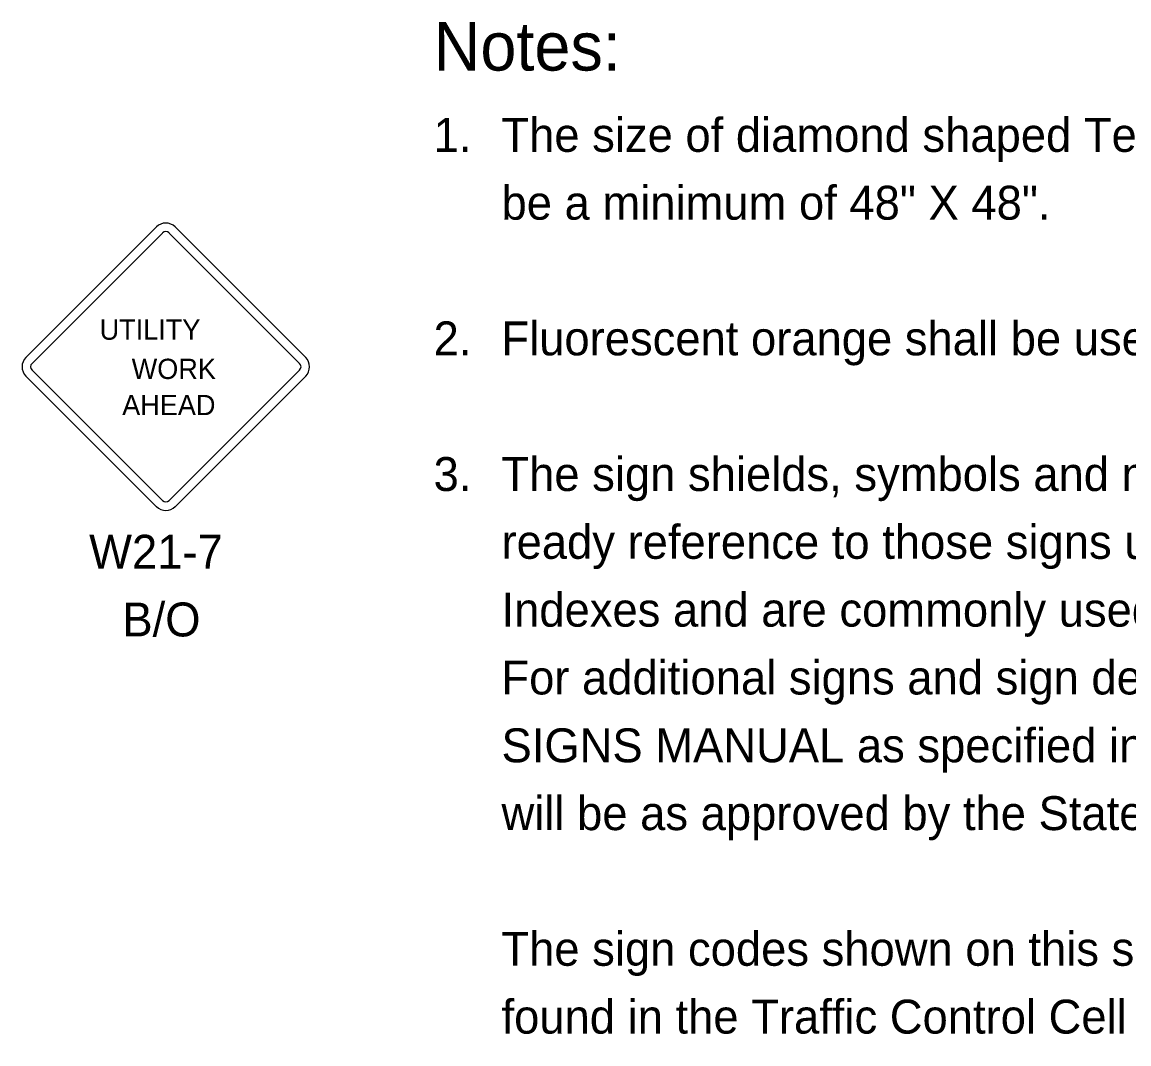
# Model space of a CAD drawing. Extents: x 10034 to 10794, y 10044 to 10499.
# Drawn here: x 10507.5 to 10621.7, y 10164.6 to 10270 of the extents above; entities that cross this region are included whole.
import ezdxf

# ---------------------------------------------------------------- set-up
doc = ezdxf.new("R2010")
doc.units = 0
for name, color, linetype in [('DSText', 7, 'Continuous'), ('DSTitle', 7, 'Continuous'), ('PlotBorder_dp', 7, 'Continuous')]:
    doc.layers.add(name, color=color, linetype=linetype)

msp = doc.modelspace()

# ---------------------------------------------------------------- linework, layer by layer
at = {"layer": 'DSText'}
for p, q in [((10507.86, 10235.41), (10521.34, 10248.89)), ((10523.25, 10248.89), (10536.73, 10235.41)), ((10521.34, 10220.02), (10507.86, 10233.5)), ((10536.73, 10233.5), (10523.25, 10220.02))]:
    msp.add_line(p, q, dxfattribs=at)
for centre, start, end in [((10522.29, 10247.93), 45, 135), ((10508.82, 10234.46), 135, 225), ((10535.76, 10234.46), 315, 45), ((10522.3, 10220.99), 225, 315)]:
    msp.add_arc(centre, 1.36, start, end, dxfattribs=at)
at = {"layer": 'DSTitle'}
for p, q in [((10508.49, 10234.8), (10521.95, 10248.26)), ((10522.64, 10248.26), (10536.1, 10234.8)), ((10521.95, 10220.65), (10508.49, 10234.11)), ((10536.1, 10234.11), (10522.64, 10220.65))]:
    msp.add_line(p, q, dxfattribs=at)
for centre, start, end in [((10522.29, 10247.92), 45, 135), ((10508.83, 10234.46), 135, 225), ((10535.75, 10234.46), 315, 45), ((10522.29, 10221), 225, 315)]:
    msp.add_arc(centre, 0.49, start, end, dxfattribs=at)

# ---------------------------------------------------------------- texts
at = {"layer": 'PlotBorder_dp'}
for s, height, p in [('Notes:', 5, (10549.92, 10265.03)), ('1.', 3.5, (10549.92, 10256.64)), ('The size of diamond shaped Temporary Traffic Control (TTC) warning signs shall ', 3.5, (10556.92, 10256.64)), ('be a minimum of 48" X 48".', 3.5, (10556.93, 10249.64)), ('UTILITY', 2.089, (10515.46, 10237.25)), ('2.', 3.5, (10549.92, 10235.64)), ('Fluorescent orange shall be used for all orange colored work zone signs.', 3.5, (10556.92, 10235.64)), ('WORK', 2.089, (10518.77, 10233.2)), ('AHEAD', 2.089, (10517.79, 10229.47)), ('The sign shields, symbols and messages contained on this sheet are provided for ', 3.5, (10556.92, 10221.64)), ('3.', 3.5, (10549.92, 10221.64)), ('ready reference to those signs used in the development of the 102 Series of ', 3.5, (10556.93, 10214.64)), ('W21-7', 3.5, (10514.38, 10213.62)), ('Indexes and are commonly used in the development of traffic control plans.', 3.5, (10556.93, 10207.64)), ('B/O', 3.5, (10517.81, 10206.63)), ('For additional signs and sign detail information refer to the STANDARD HIGHWAY ', 3.5, (10556.92, 10200.64)), ('SIGNS MANUAL as specified in the MUTCD. Special signs for traffic control plans ', 3.5, (10556.93, 10193.64)), ('will be as approved by the State Traffic Plans Engineer.', 3.5, (10556.93, 10186.64)), ('The sign codes shown on this sheet are for the purpose of identifying cell names ', 3.5, (10556.92, 10172.64)), ('found in the Traffic Control Cell Library (TCZ.Cel).', 3.5, (10556.93, 10165.64))]:
    msp.add_text(s, height=height, dxfattribs=at).set_placement(p)

doc.saveas('drawing.dxf')
